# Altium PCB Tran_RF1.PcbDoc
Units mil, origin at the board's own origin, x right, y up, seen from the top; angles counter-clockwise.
Board outline 5000 x 4000 mil, 2 copper layers (Top Layer, Bottom Layer); 21 components, 22 nets, 91 pads, 5 vias.
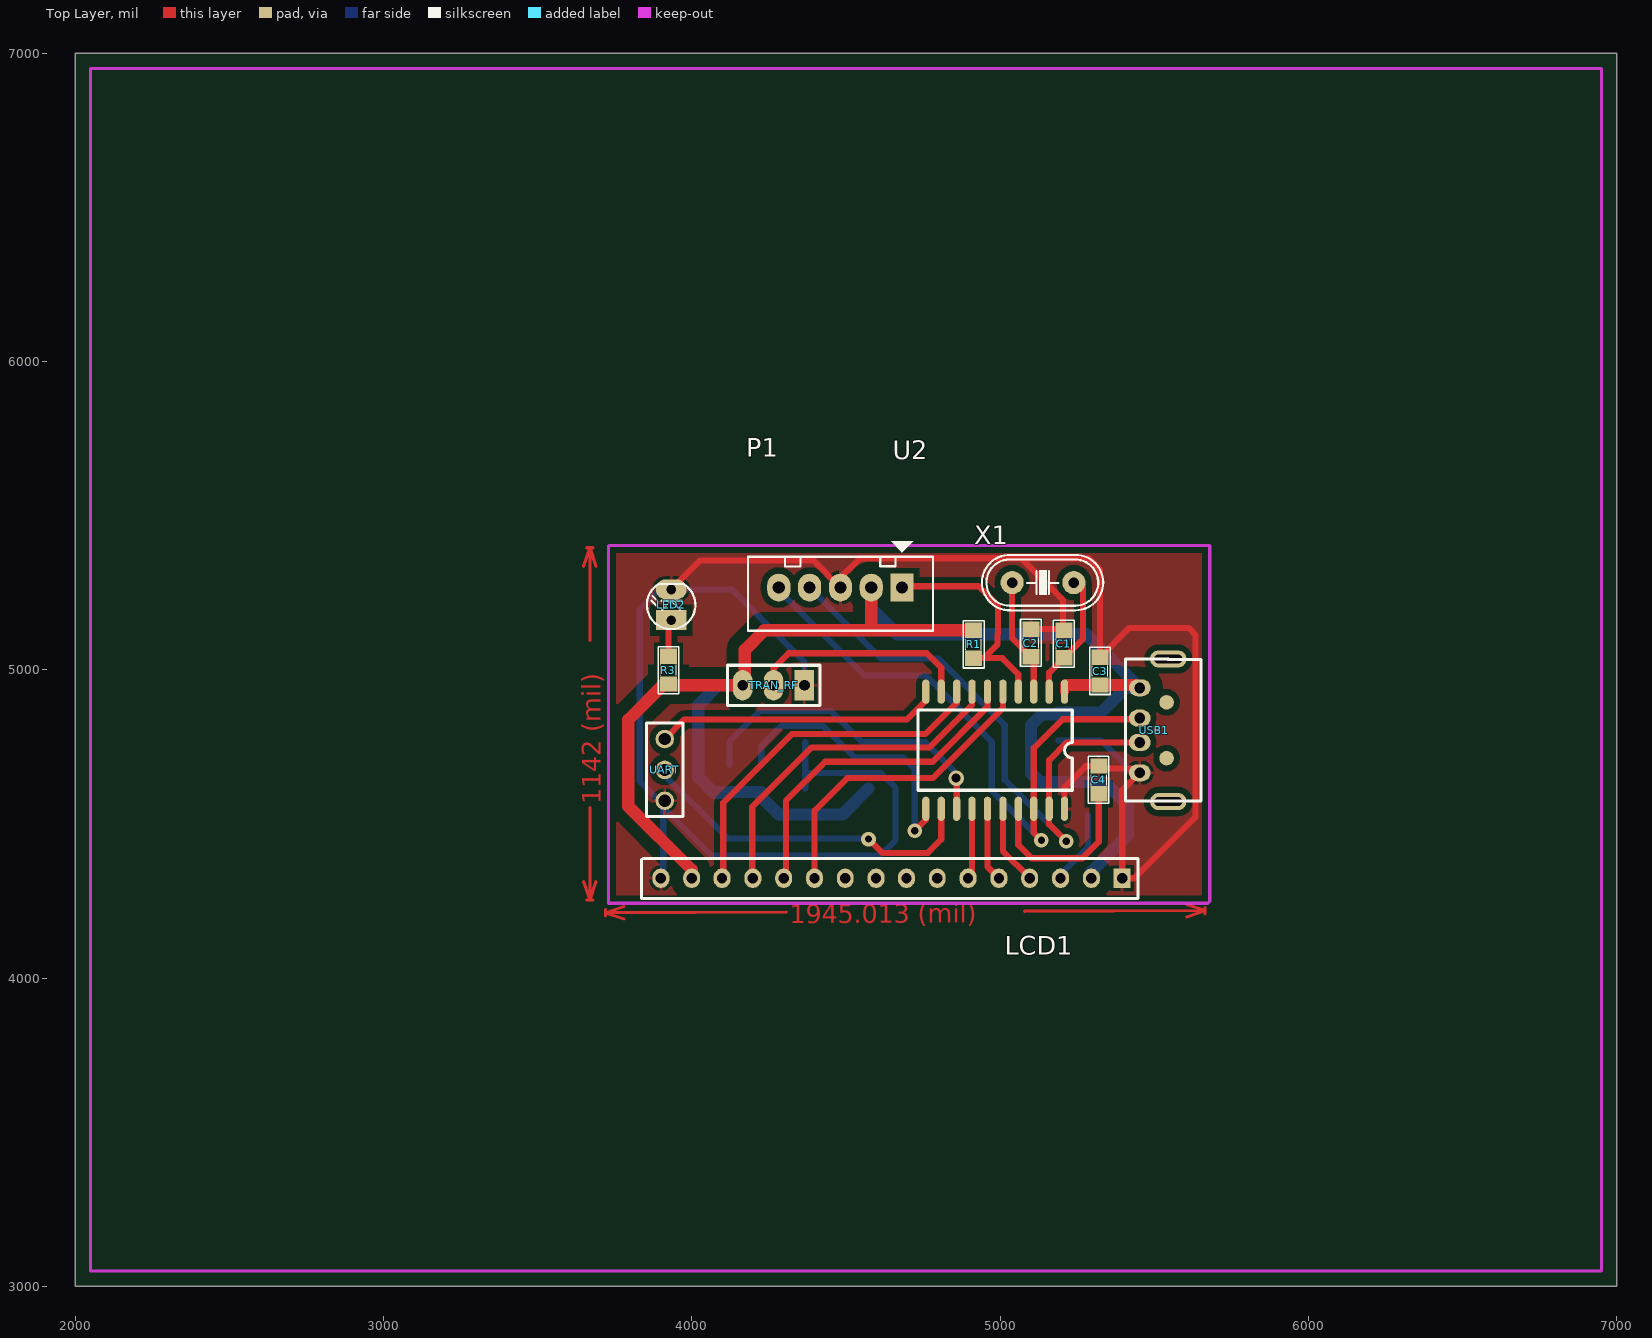
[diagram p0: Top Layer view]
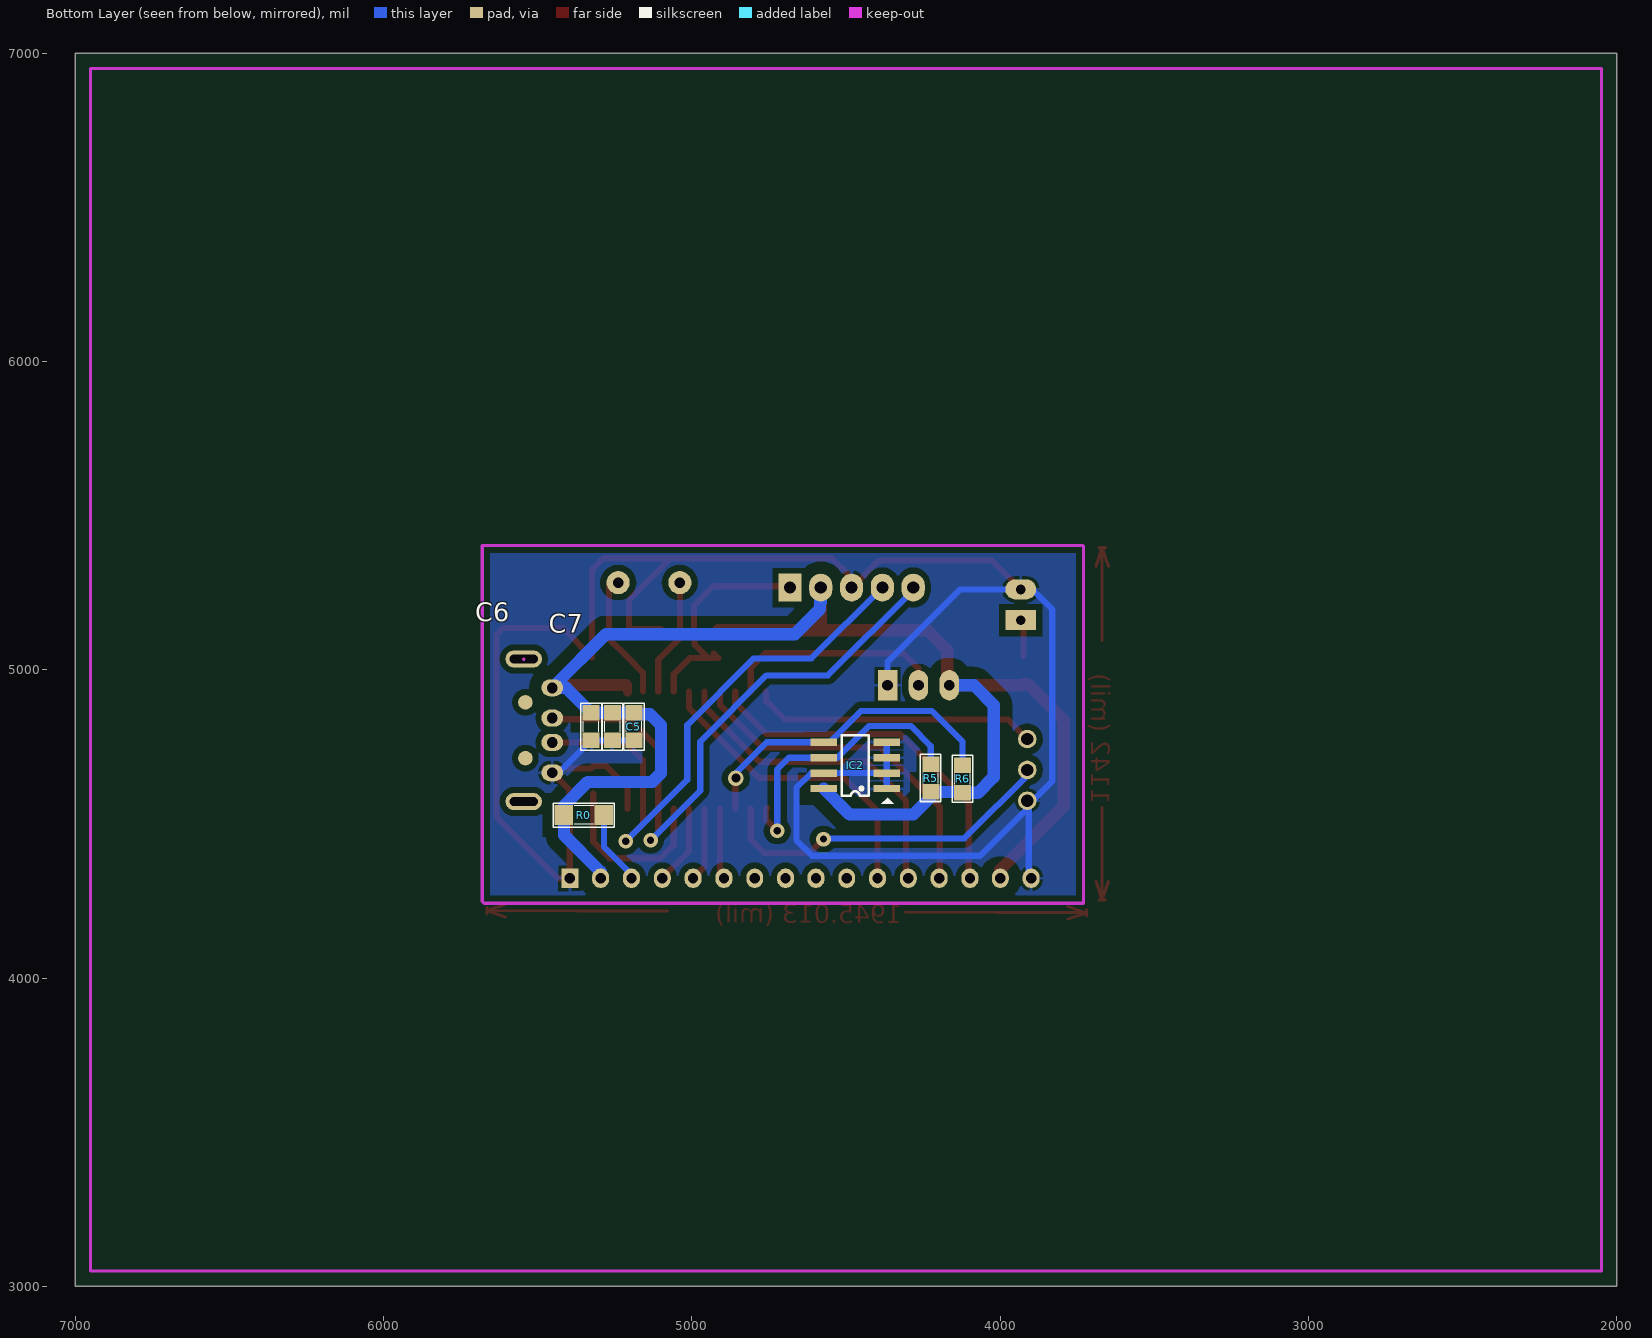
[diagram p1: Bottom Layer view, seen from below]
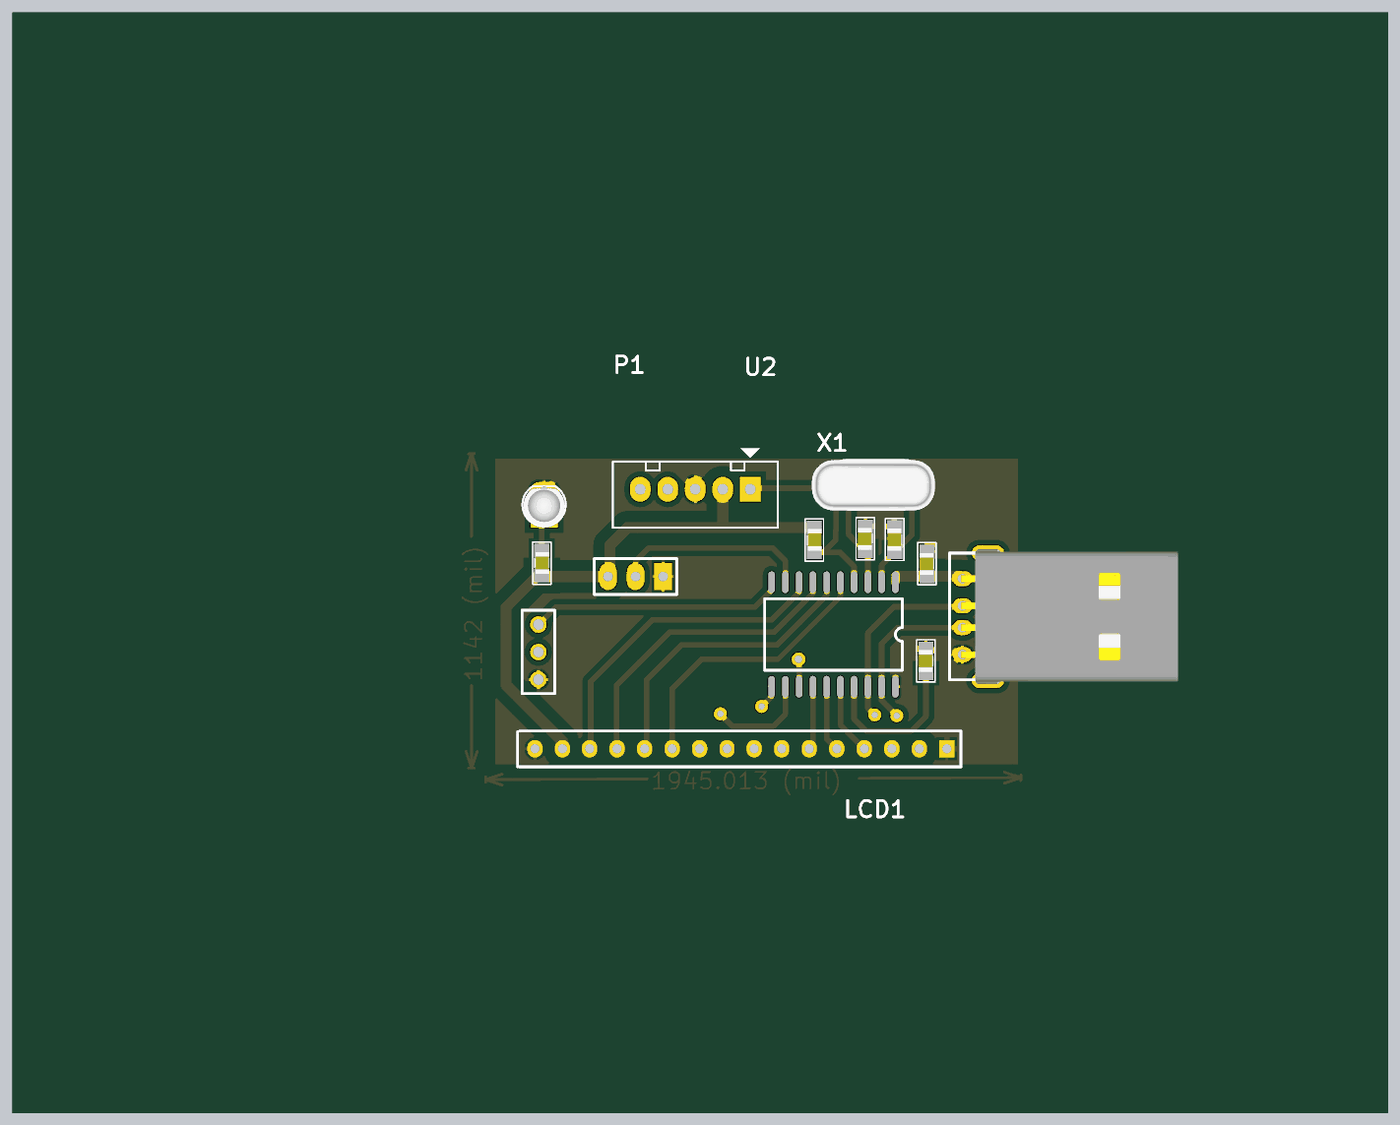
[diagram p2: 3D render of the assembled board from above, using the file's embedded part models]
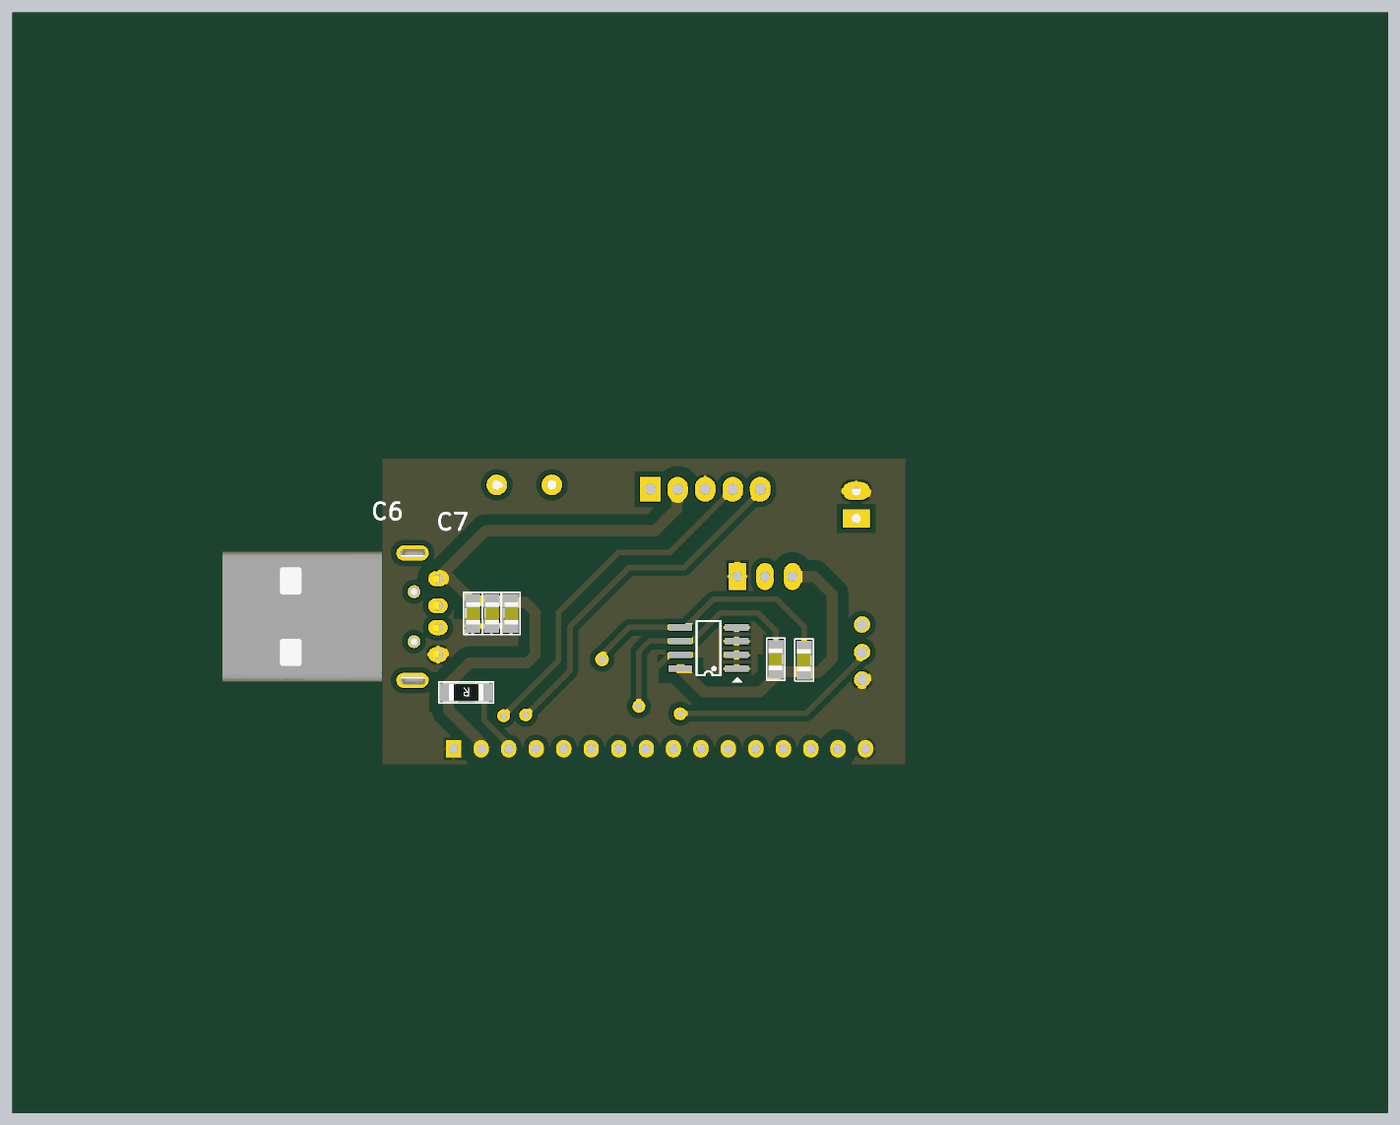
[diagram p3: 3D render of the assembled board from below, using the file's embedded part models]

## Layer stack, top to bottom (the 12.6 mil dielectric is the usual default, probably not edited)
Top Layer: signal copper 1.4
Dielectric: core 12.6, FR-4, Dk 4.8
Bottom Layer: signal copper 1.4

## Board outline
2000,3000 7000,3000 7000,7000 2000,7000

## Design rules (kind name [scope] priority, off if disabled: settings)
Clearance VCC [InNet('VCC')] p1: gap=40
Clearance [All] p2: gap=20
PolygonConnect [All] p1: connectstyle=Relief reliefconductorwidth=10 reliefentries=4 polygonreliefangle="90 Angle" airgapwidth=10
RoomDefinition Tran_RF [InComponentClass('Tran_RF')] p1: confinementstyle=ConfineIn formatcopy=TRUE lockcomponents=FALSE outline 0,0 2000,0 2000,1000 0,1000
RoutingVias [All] p1: holewidth=25 width=40 viastyle="Through Hole" minholewidth=28 minwidth=50 maxholewidth=28 maxwidth=50
SolderMaskExpansion [All] p1: expansion=4
Width VCC_1 [InNet('VCC')] p1: maxlimit=40 minlimit=40 preferedwidth=40
Width [All] p2: maxlimit=20 minlimit=20 preferedwidth=20
28 further rules are at their usual default settings.

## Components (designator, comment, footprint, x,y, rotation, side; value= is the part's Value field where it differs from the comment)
C1 "33pF" SM-0805 5207,5084 r270 top
C2 "33pF" SM-0805 5100,5087 r270 top
C3 "103" SM-0805 5324,4996 r270 top
C4 "103" SM-0805 5320,4643 r270 top
C5 "103" SM-0805 5188,4816 r90 bottom
C6 "103" SM-0805 5258,4816 r90 bottom
C7 "103" SM-0805 5327,4816 r90 bottom
IC2 "24Cxx" SO-G8 4470,4690 r90 bottom
LCD1 "LCD16x2A" LCD 5396,4324 r180 top
LED2 "LED" LED-3 3933,5161 r90 top
P1 "MACH NAP" CON5 4682,5267 r180 top
R0 "1k" SM-1206 5350,4529 r0 bottom
R1 "10K" SM-0805 4914,5083 r90 top
R3 "220" SM-0805 3924,4999 r90 top
R5 "1k" SM-0805 4225,4649 r270 bottom
R6 "1k" SM-0805 4122,4646 r270 bottom
TRAN_RF "JP3" HEADER1x3 4365,4950 r180 top
U2 "PIC18F14K50-I/P" SOP-20 5209,4929.36 r270 top
UART "JP3" CON3 3912,4674 r90 top
USB1 "USB-S" USB-A-RA 5456,4804 r90 top
X1 "8Mhz" XT2 5139,5283 r0 top

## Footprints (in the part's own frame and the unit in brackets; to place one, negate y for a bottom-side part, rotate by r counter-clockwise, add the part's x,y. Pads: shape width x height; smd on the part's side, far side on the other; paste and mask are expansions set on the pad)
CON3 [mil] "3-Pin Connector; pitch 2.54mm"
  round 60 hole 39.37: 1(-98.43,0) 2(1.57,0) 3(101.57,0)
  silkscreen extent -150,-59 154,59
CON5 [mil] "CON5"
  rect 75x90 hole 39.37: 1(0,0)
  oval 75x90 hole 39.37: 2(100,0) 3(200,0) 4(300,0) 5(400,0)
  silkscreen extent -100,-150 500,140, body extent -103,-106 505,146, height 276
HEADER1x3 [mm]
  rect 1.6x2.5 hole 0.9: 1(0,0)
  oval 1.6x2.5 hole 0.9: 2(2.54,0) 3(5.08,0)
  silkscreen extent -1.27,-1.65 6.35,1.65
LCD [mm]
  rect 1.4x1.6 hole 0.85 mask+0: 1(0,0)
  oval 1.4x1.6 hole 0.85 mask+0: 2(2.54,0) 3(5.08,0) 4(7.62,0) 5(10.16,0) 6(12.7,0) 7(15.24,0) 8(17.78,0) 9(20.28,0) 10(22.82,0) 11(25.351,0) 12(27.891,0) 13(30.431,0) 14(32.971,0) 15(35.471,0) 16(38.011,0)
  silkscreen extent -1.3,-1.63 39.61,1.67
LED-3 [mil] "LED 2 PIN, 3ly Only colour"
  rect 65x100 hole 32: 1(0,0)
  oval 65x100 hole 32: 2(100,0)
  silkscreen extent -29,-78 118,79, body extent -29,-75 109,75, height 256
SM-0805 [mil] "Compoment SMD 80x50mil"
  rect 50x55 smd: 1(-45,0) 2(45,0)
  silkscreen extent -77,-34 76,33, body extent -40,-27 40,23, height 24
SM-1206 [mil] "Compoment SMD 120x60mil"
  rect 60x65 smd: 1(-65,0) 2(65,0)
  silkscreen extent -99,-38 99,39, body extent -83,-35 83,36, height 25
SO-G8 [mm] "Small Outline; 8 Leads; Body Width 3.9 mm; Pitch 1.27 mm"
  rect 0.6x2.2 smd: 1(-1.905,-2.6) 2(-0.635,-2.6) 3(0.635,-2.6) 4(1.905,-2.6) 5(1.905,2.6) 6(0.635,2.6) 7(-0.635,2.6) 8(-1.905,2.6)
  silkscreen extent -3.18,-3.17 2.5,1.1
SOP-20 [mm]
  oval 2x0.6 smd: 1(0,0) 2(0,-1.27) 3(0,-2.54) 4(0,-3.81) 5(0,-5.08) 6(0,-6.35) 7(0,-7.62) 8(0,-8.89) 9(0,-10.16) 10(0,-11.43) 11(9.652,-11.43) 12(9.652,-10.16) 13(9.652,-8.89) 14(9.652,-7.62) 15(9.652,-6.35) 16(9.652,-5.08) 17(9.652,-3.81) 18(9.652,-2.54) 19(9.652,-1.27) 20(9.652,0)
  silkscreen extent 1.52,-12.06 8.13,0.64
USB-A-RA [mm] "USB Type A"
  oval 1.4x1.8 hole 0.9: 1(3.5,0.08) 2(1,0.08) 3(-1,0.08) 4(-3.5,0.08)
  oval 1.4x3 hole 0.7 slot 2.3 at 90 deg: HOLE(-5.875,-2.27) HOLE(5.875,-2.27)
  round 1.2 all layers, no hole: HOLE(-2.3,-2.13) HOLE(2.3,-2.13)
  Keep-Out Layer lines w0.254: 5.842,-2.27 5.875,-2.27
  silkscreen extent -5.84,-4.95 5.87,1.27, body extent -6.25,-19.8 6.25,0.23, height 2.18
XT2 [mil] "Footpin for Crystal 2 pin"
  round 75 hole 34: 1(-100,0) 2(100,0)
  silkscreen extent -198,-90 195,90, body extent -233,-93 213,90, height 138

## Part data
C1 C2 C3 C4 C5 C6 C7: library part CM, "Cap SMD"
IC2: "Standard 2-Wire Bus Interface Serial EEPROM"
LCD1: library part LCD16x2, "LCD dipslay 16 char, 2 line"
LED2: "LED Single colour Green and Red"
P1: library part "Header 5H", "Header, 5-Pin, Right Angle"
R0 R1 R3 R5 R6: library part R, "Resistor 1/4W"
TRAN_RF UART: library part Con3, "Connector 3"
U2: "USB Flash Microcontroller with nanoWatt XLP Technology, 20-pin PDIP, Industrial Temperature"
USB1: library part USB_S, "USB connector"
X1: library part XT2, "Crystal For all Crystal 2pin."

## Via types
v1: diameter 47.24, hole 23.62, Top Layer to Bottom Layer, 4 vias
v2: diameter 50, hole 28, Top Layer to Bottom Layer, 1 vias

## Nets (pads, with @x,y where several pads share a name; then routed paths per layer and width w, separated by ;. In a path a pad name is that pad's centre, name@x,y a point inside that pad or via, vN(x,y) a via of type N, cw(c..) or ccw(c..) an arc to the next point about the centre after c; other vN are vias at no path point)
D4: LCD1.11 U2.5 | length 1021.3
  Top Layer w20: LCD1.11 4397.93,4542.93 4504,4649 4782,4649 5009,4876 U2.5
D5: LCD1.12 U2.6 | length 1083.6
  Top Layer w20: LCD1.12 4305,4331.07 4305,4575 4432,4702 4781,4702 4959,4880 U2.6
D6: LCD1.13 U2.7 | length 1125.3
  Top Layer w20: LCD1.13 4196,4325.93 4196,4556 4388,4748 4770,4748 4909,4887 U2.7
D7: LCD1.14 U2.8 | length 1174.3
  Top Layer w20: LCD1.14 4102,4328.07 4102,4569 4325,4792 4758,4792 4859,4893 U2.8
D+/PGD: P1.4 U2.19 USB1.3 | length 1880.7
  Top Layer w20: v1(5214,4444) 5159,4499 U2.19 5159,4707 5216.63,4764.63 USB1.3
  Bottom Layer w20: P1.4 4612,5037 4799,5037 5015,4821 5015,4643 v1(5214,4444)
D-/PGC: P1.5 U2.18 USB1.2 | length 1983
  Top Layer w20: v1(5134,4447) 5109,4472 U2.18 5109,4746 5202.99,4839.99 5449.47,4839.99 USB1.2
  Bottom Layer w20: P1.5 4282,5259 4559,4982 4758,4982 4973,4767 4973,4608 v1(5134,4447)
EN: LCD1.6 U2.14 | length 212.4
  Top Layer w20: LCD1.6@4909,4337 U2.14
GND: C1.1 C2.1 C3.1 C4.1 C5.1 C6.1 C7.1 IC2.1 IC2.2 IC2.3 IC2.4 IC2.7 LCD1.1 LCD1.16 LED2.2 P1.3 TRAN_RF.1 U2.20 UART.1 USB1.4 | length 7641.5
  Top Layer w20: LED2.2 4027,5355 4394,5355 P1.3 4482,5298.24 4545.76,5362 5068,5362 ; C2.1 C1.1@5204,5132 ; C1.1 C1.1@5204,5132 ; U2.20 5209,4620 5277,4688 C4.1 5328,4680 5439.06,4680 USB1.4 5396,4609.35 LCD1.1 5435,4324 5634,4523 5634,5113 5611,5136 5419,5136 C3.1 5324,5325 5287,5362 5068,5362 ; 5068,5362 5204,5226 C1.1@5204,5132
  Bottom Layer w20: LCD1.16 3907,4331.5 3907,4548.57 UART.1@3912,4553.57 ; IC2.1 IC2.2 ; IC2.4 IC2.3 IC2.2 ; TRAN_RF.1@4367.64,4947.36 TRAN_RF.1 4365,5026 4130,5261 LED2.2 3896,5261 3831,5196 3831,4638.57 3894,4575.57 UART.1 UART.1@3912,4553.57 ; C5.1 C6.1 C7.1 5431.8,4666.2 USB1.4 ; UART.1@3912,4553.57 3912,4550 4065,4397 4610,4397 4661,4448 4661,4617 4613,4665 IC2.7 IC2.2
MCLR: P1.1 R1.1 U2.4 | length 772.2
  Top Layer w20: P1.1 4686,5271 4930,5271 4993.11,5207.89 4993.11,5117.11 4991.5,5115.5 4991.5,5082.29 4947.21,5038 ; R1.1@4929,5053 R1.1 4947.21,5038 ; U2.4 5059,4986 5007,5038 4947.21,5038
NetC4_2: C4.2 U2.17 | length 574.1
  Top Layer w20: U2.17 5059,4432 5102,4389 5267,4389 5320,4442 C4.2
NetLED2_1: LED2.1 R3.2 | length 120.7
  Top Layer w20: R3.2 3924,5152 LED2.1
OSC1: C1.2 U2.2 X1.2 | length 422.8
  Top Layer w20: U2.2 5159,4991 C1.2 5269,5101 5269,5272 5258,5283 X1.2
OSC2: C2.2 U2.3 X1.1 | length 382.6
  Top Layer w20: X1.1 5039,5103 C2.2 5109,5033 U2.3
RS: LCD1.4 U2.16 | length 261.4
  Top Layer w20: U2.16 5009,4412 5096,4325 LCD1.4
RW: LCD1.5 U2.15 | length 240.7
  Top Layer w20: U2.15 4959,4361 LCD1.5
RX: U2.12 UART.2 | length 1131.5
  Top Layer w20: v1(4573,4451) 4618,4406 4765,4406 4809,4450 U2.12
  Bottom Layer w20: UART.2@3903,4666.57 4116.29,4453.29 4570.71,4453.29 v1(4573,4451)
SCL: IC2.6 R5.1 U2.11 | length 931.3
  Top Layer w20: v1(4723,4478) 4759,4514 U2.11 U2.11@4756.36,4552
  Bottom Layer w20: R5.1 4225,4753 4290,4818 4425,4818 4528,4715 IC2.6 4685,4715 4723,4677 v1(4723,4478)
SDA: IC2.5 R6.1 U2.13 | length 1052.6
  Top Layer w20: v2(4857,4649) 4859,4647 U2.13
  Bottom Layer w20: R6.1 4122,4767 4222,4867 4451,4867 4553,4765 IC2.5 4757,4765 4857,4665 v2(4857,4649)
TRAN_RF: TRAN_RF.2 U2.9 | length 716.4
  Top Layer w20: TRAN_RF.2 4265,5005 4314,5054 4762,5054 4809,5007 U2.9
TX: U2.10 UART.3 | length 927.9
  Top Layer w20: UART.3 3975.43,4839 4698,4839 4759,4900 U2.10
VCC: C3.2 C5.2 C6.2 C7.2 IC2.8 LCD1.2 LCD1.15 P1.2 R0.2 R1.2 R3.1 R5.2 R6.2 TRAN_RF.3 U2.1 USB1.1 | length 5658.6
  Top Layer w30: U2.1 5209,4946 U2.1@5214,4951
  Top Layer w40: LCD1.15 3999.5,4351.76 3794,4557.27 3794,4838 3910,4954 R3.1 3928,4950 TRAN_RF.3 4172,4957 4172,5065 4235,5128 4582,5128 ; P1.2 4582,5128 ; R1.2 4582,5128 ; U2.1@5214,4951 C3.2 5443.65,4951 USB1.1
  Bottom Layer w40: TRAN_RF.3 4085,4950 4021,4886 4021,4652 4072,4601 R6.2 4125,4604 R5.2 4225,4588 4282,4531 4488.36,4531 IC2.8 ; 4582,5219 P1.2 4584.5,5264.5 4584.5,5197.15 4665.65,5116 5278.65,5116 USB1.1 5407.8,4941.8 C7.2 C6.2 C5.2 5183,4856 5135.65,4856 5100,4820.35 5100,4665 5129,4636 5338,4636 5415,4559 R0.2 5415,4464 5296,4345 LCD1.2
VSS: LCD1.3 R0.1 | length 241.9
  Bottom Layer w20: LCD1.3 5196,4337.62 5285,4426.62 R0.1
pads on no net: LCD1.7 LCD1.8 LCD1.9 LCD1.10 USB1.HOLE
copper on no net: | length 2359.4
  Top Layer w10: 3649,4314 3669,4254 ; 3649,5336 3669,5396 ; 3659,4254 3679,4254 ; 3659,5396 3679,5396 ; 3669,4554.08 3669,4254 ; 3669,5095.92 3669,5396 ; 3689,4314 3669,4254 ; 3689,5336 3669,5396 ; 3719.96,4222 3720.04,4202 ; 3779.93,4232.22 3720,4212 ; 3780.07,4192.22 3720,4212 ; 4306.62,4214.11 3720,4212 ; 5078.38,4216.89 5665,4219 ; 5604.93,4238.78 5665,4219 ; 5605.07,4198.78 5665,4219 ; 5664.96,4229 5665.04,4209

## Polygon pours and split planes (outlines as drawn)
GND on Top Layer "Top Layer-No Net" (solid, remove dead copper, pour order 12): 3729,5401 3729,4252 3738,4243 5674,4243 5674,5397 5680,5403 5678,5401 3729,5401
GND on Bottom Layer "Top Layer-No Net" (solid, remove dead copper, pour order 14): 3729,5401 5678,5401 5680,5403 5680,4249 3735,4249 3729,4243 3731,4245 3731,5403

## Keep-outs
Keep-Out Layer:
  lines w10: 2050,3050 6950,3050 6950,6950 2050,6950 2050,3050 ; 3729,4243 3729,5390 3729,5401 3731,5403 3797,5403 5680,5403 5680,4249 5674,4243 5584,4243 3729,4243

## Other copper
Top Layer:
  text "1142 (mil)" at 3704.99,4564.08 h60 r90
  text "1945.013 (mil)" at 4316.75,4178.16 h60 r0.21

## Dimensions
2050,3050 to 6950,3050 on Mechanical 1
2050,3050 to 2050,6950 on Mechanical 1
